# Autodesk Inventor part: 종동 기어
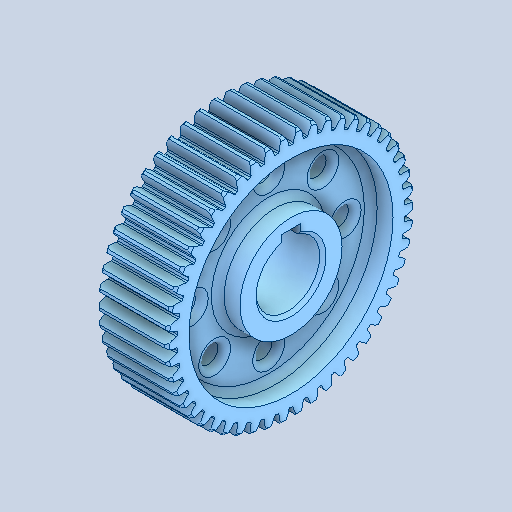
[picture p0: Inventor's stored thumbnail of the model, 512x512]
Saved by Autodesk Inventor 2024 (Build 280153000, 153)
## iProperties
Created: 2025-11
Part Number: 종동 기어
Material: 강철, 탄소
Document SubType Name: Modeling
Designer: Eud07
Density: 7.85 g/cm^3
Appearance: 기본값
Author: jhkim
Sending System: Autodesk Inventor 2026
Preprocessor: ST-DEVELOPER v20.1
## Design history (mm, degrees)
node "종동 기어1"
node "솔리드2"
node "솔리드1"
